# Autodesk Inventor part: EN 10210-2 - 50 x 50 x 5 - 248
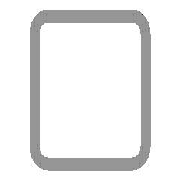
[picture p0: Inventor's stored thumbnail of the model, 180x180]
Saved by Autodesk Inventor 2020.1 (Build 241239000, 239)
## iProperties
IsCustomPart: 1
_CCFamilyMember: 16
_CCFamilyDisplayName: DIN EN 10210-2 (USAS B17.1 quadratisch) - Rohrleitung — In Klammern angegebene Größen wurden aufgehoben
_FrameMemberDoc: Frame Member File
_Version: 15.0.0
_GetPNFromCC: 1
Created: 2019-01
Part Number: EN 10210-2 - 50 x 50 x 5 - 248
Material: Steel, Mild
Description: Rohrleitung
Document SubType Name: Modeling
Standard: DIN
Designer: lutzd
Standard Revision: 2006-07
Standards Organization: DIN
Language: de-DE
Size Designation: 50 x 50 x 5
Categories: <MemberInstance><Categories><Category DisplayName="Profile" InternalName="089c4875-fa83-4c05-b084-43b9cc11f5ed" Mnemonic="GRDR"><CategoryParameter DisplayName="
Stock Number: 50 x 50 x 5
Mass: 216.2 g
Surface Area: 857.742 cm^2
Volume: 216.2 cm^3
Density: 1 g/cm^3
Appearance: Semi-Polished
G_L: 248,000 mm
G_W: 50,000 mm
G_H: 50,000 mm
DocNumber: ADSK-014238
Folder: .
Dimensions: 50x50x248 mm
Mass: 0,216 kg
Title: Profil-Bauteil
Author: lutzd
Revision Number: -
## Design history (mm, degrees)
node "Startebene"
node "Endebene"
sketch "Skizze"
  geometry: L1 (-25, -17.5)-(-25, 17.5); L2 (-17.5, 25)-(17.5, 25); L3 (25, 17.5)-(25, -17.5); L4 (17.5, -25)-(-17.5, -25); L5 (-15, 20)-(15, 20); L6 (20, 15)-(20, -15); L7 (15, -20)-(-15, -20); L8 (-20, -15)-(-20, 15); L9 (0, 37.175)-(0, -37.175) reference; L10 (-37.175, 0)-(37.175, 0) reference; A1 r 7.5 centre (-17.5, -17.5) between (-25, -17.5) and (-17.5, -25); A2 r 7.5 centre (-17.5, 17.5) between (-17.5, 25) and (-25, 17.5); A3 r 7.5 centre (17.5, 17.5) between (25, 17.5) and (17.5, 25); A4 r 7.5 centre (17.5, -17.5) between (17.5, -25) and (25, -17.5); A5 r 5 centre (-15, -15) between (-20, -15) and (-15, -20); A6 r 5 centre (-15, 15) between (-15, 20) and (-20, 15); A7 r 5 centre (15, 15) between (20, 15) and (15, 20); A8 r 5 centre (15, -15) between (15, -20) and (20, -15)
  constraints: 16 end point, 16 point on circle, 16 tangent, 8 centre point, 6 equal radius, 4 parallel, 2 perpendicular, 2 other
  dimensions: "d7" = 7.5 radius of A1 (= G_IR); "d10" = 50 distance between parallel lines of L2 L4 (= G_H); "d11" = 50 distance between parallel lines of L1 L3 (= G_W); "d12" = 5 distance between parallel lines of L3 L6 (= G_T); "d15" = 25 distance between parallel lines of L2 L10 (= 0.5 x d10); "d16" = 25 distance between parallel lines of L9 L3 (= 0.5 x d11); "d19" = 5 radius of A5 (= G_T); "d20" = 5 distance between parallel lines of L4 L7 (= G_T)
extrude "Körper" new body sketch "Skizze" stored distance "d3" = 248 (= G_L); taper "d4" = 0 deg
node "Driven Length"
  sketch "Sketch3"
    geometry: L1 (0, 0)-(10, 0) reference
    constraints: 2 end point, 1 horizontal
  workplane "Work Plane3"
  sketch "Sketch4"
    geometry: L1 (-2, 0)-(12, 0) reference; L2 (-2, 248)-(12, 248) reference
    dimensions: "d18" = 248 distance between parallel lines of L1 L2 (derived)
sketch "Skizze5"
  geometry: L1 (0, -35)-(0, 0) reference; L2 (0, -17.5)-(236, -17.5); 2 further points
  constraints: 2 end point, 1 coincident, 1 horizontal, 1 point on line
  dimensions: "d21" = 64 distance of point (172, -17.5) point (236, -17.5); "d22" = 172 distance from line of L1 point (172, -17.5)
hole "Bohrung1" sketch "Skizze5" at (236, -17.5), (172, -17.5) diameter "d23" = 6.647; stored, may be unused: countersink angle "d27" = 90 deg, drill point angle "d29" = 118 deg; dims "d24" = 16, "d25" = 4, "d26" = 2, "d28" = 8
body "Solid1"
other parameters: "G_W" = 50 [user parameter; used in 1 equation term], "G_H" = 50 [user parameter; used in 1 equation term], "G_T" = 5 [user parameter; used in 3 equation terms], "G_IR" = 7.5 [user parameter; used in 1 equation term], "G_L" = 248 (= d18) [user parameter; used in 1 equation term], "G_OFFSET_START" = 0 [user parameter; used in 1 equation term], "G_OFFSET_END" = 0 [user parameter; used in 1 equation term], "d13" = 0 (computed from G_OFFSET_START), "d14" = 248 (= G_OFFSET_END + B_L), "B_L" = 248 [user parameter; used in 1 equation term], "d17" = 90 deg
